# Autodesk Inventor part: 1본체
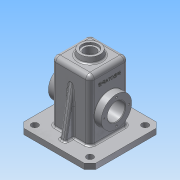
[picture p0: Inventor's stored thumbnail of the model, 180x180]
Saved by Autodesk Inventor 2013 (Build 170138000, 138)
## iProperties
Created: 2016-02
Part Number: 1본체
Material: 알루미늄 6061
Document SubType Name: Modeling
Designer: Administrator
Density: 2.71 g/cm^3
Mass: 929.197 g
Surface Area: 1052.48 cm^2
Volume: 342.877 cm^3
Author: Administrator
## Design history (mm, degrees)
sketch "스케치1"
  geometry: L1 (-65, 65)-(65, 65); L2 (65, 65)-(65, -65); L3 (65, -65)-(-65, -65); L4 (-65, -65)-(-65, 65); L5 (-65, 65)-(65, -65); 2 further points
  constraints: 10 end point, 2 parallel, 1 coincident, 1 horizontal, 1 midpoint, 1 perpendicular
  dimensions: "d0" = 130 distance of L1.end L2.end; "d2" = 130 distance of L1.start L1.end
extrude "돌출1" new body sketch "스케치1" distance "d3" = 10; taper "d4" = 0 deg
chamfer "모따기1" distance "d5" = 10; stored, may be unused: second distance "d6" = 2, angle "d7" = 45 deg
sketch "스케치2"
  geometry: C1 r 6 at (-50, 50); 1 further point
  constraints: 1 centre point
  dimensions: "d8" = 50 horizontal distance of point (0, 0) C1.centre; "d9" = 50 horizontal distance of point (0, 0) C1.centre; "d10" = 12 diameter of C1
extrude "돌출2" cut sketch "스케치2" stored distance "d11" = 10; taper "d12" = 0 deg
sketch "스케치3"
  geometry: L1 (65, -55)-(55, -65) reference; L2 (-35, 35)-(35, 35); L3 (35, 35)-(35, -35); L4 (35, -35)-(-35, -35); L5 (-35, -35)-(-35, 35); L6 (-35, 35)-(35, -35); 2 further points
  constraints: 10 end point, 2 parallel, 2 perpendicular, 1 coincident, 1 horizontal, 1 midpoint
  dimensions: "d19" = 70 distance of L2.end L3.end
extrude "돌출3" join sketch "스케치3" distance "d21" = 110; taper "d22" = 0 deg
sketch "스케치4"
  geometry: L1 (35, -35)-(35, 35) reference; L2 (35, 35)-(-35, 35) reference; L3 (-35, 35)-(-35, -35) reference; L4 (-35, -35)-(35, -35) reference; L5 (-30, 30)-(30, 30); L6 (30, 30)-(30, -30); L7 (30, -30)-(-30, -30); L8 (-30, -30)-(-30, 30); 1 further point
  constraints: 8 end point, 3 other
  dimensions: "d23" = 5 distance between parallel lines of L1 L6
extrude "돌출4" cut sketch "스케치4" distance "d24" = 115; taper "d25" = 0 deg
sketch "스케치5"
  geometry: L1 (0, 0)-(-110, 0) reference; L2 (10, 35)-(-45, 35); C1 r 27.5 at (-45, 35)
  constraints: 2 end point, 1 centre point, 1 coincident, 1 parallel
  dimensions: "d26" = 55 distance of L2.start L2.end; "d27" = 55 diameter of C1
extrude "돌출5" join sketch "스케치5" distance "d28" = 13; taper "d29" = 0 deg
sketch "스케치6"
  geometry: L1 (0, 0)-(-22.5, 0); C1 r 27.5 at (0, 0) reference; 2 further points
  constraints: 2 end point, 1 coincident, 1 horizontal
  dimensions: "d30" = 22.5 distance of L1.start L1.end
hole "구멍1" sketch "스케치6" at (-22.5, 0) diameter "d31" = 3.242; stored, may be unused: countersink angle "d35" = 90 deg, drill point angle "d37" = 118 deg; dims "d32" = 8, "d33" = 4, "d34" = 2, "d36" = 10
sketch "스케치7"
  geometry: C1 r 27.5 at (0, 0) reference; C2 r 16 at (0, 0); 1 further point
  constraints: 1 centre point, 1 coincident
  dimensions: "d42" = 32 diameter of C2
extrude "돌출6" cut sketch "스케치7" stored distance "d44" = 13; taper "d45" = 0 deg
sketch "스케치8"
  geometry: L1 (-30, 0)-(-30, 115) reference; L2 (-48, 71)-(-30, 71) reference; L3 (-35, 82.5)-(-48, 82.5) reference; L4 (-30, 82.5)-(-23, 75.5); L5 (-23, 75.5)-(-23, 71); L6 (-23, 71)-(-30, 71); L7 (-35, 27.5)-(-48, 27.5) reference; L8 (-30, 82.5)-(-30, 71); L9 (-48, 39)-(-48, 71) reference; L10 (-48, 55)-(-30, 55); 1 further point
  constraints: 10 end point, 4 perpendicular, 2 point on line, 1 midpoint
  dimensions: "d46" = 7 distance between parallel lines of L5 L1; "d47" = 135 deg angle of L1 L4; "d48" = 55 distance from line of L4.start L7
revolve "회전1" sketch "스케치8" stored, may be unused: angle "d49" = 90 deg
sketch "스케치9"
  geometry: C1 r 27.5 at (0, 0) reference; C2 r 16 at (0, 0); 1 further point
  constraints: 1 centre point, 1 coincident
  dimensions: "d51" = 32 diameter of C2
extrude "돌출7" cut sketch "스케치9" stored distance "d53" = 13; taper "d54" = 0 deg
chamfer "모따기2" distance "d55" = 1; stored, may be unused: second distance "d56" = 2, angle "d57" = 45 deg
sketch "스케치10"
  geometry: C1 r 20 at (0, 0); 1 further point
  constraints: 1 centre point, 1 coincident
  dimensions: "d59" = 40 diameter of C1
extrude "돌출8" join sketch "스케치10" distance "d61" = 10; taper "d62" = -10 deg
sketch "스케치11"
  geometry: C1 r 18.237 at (0, 0) reference; C2 r 14 at (0, 0)
  constraints: 1 centre point, 1 coincident
  dimensions: "d63" = 28 diameter of C2
extrude "돌출9" cut sketch "스케치11" distance "d65" = 4; taper "d66" = 0 deg
sketch "스케치12"
  geometry: C1 r 14 at (0, 0) reference; C2 r 10.5 at (0, 0)
  constraints: 1 centre point, 1 coincident
  dimensions: "d67" = 21 diameter of C2
extrude "돌출10" cut sketch "스케치12" stored distance "d69" = 4; taper "d70" = 0 deg
fillet "모깎기4" dims "d71" = 3
sketch "스케치13"
  geometry: L1 (35, 10)-(35, 120) reference; L2 (44, 10)-(56, 10) reference; L3 (55, 10)-(-55, 10) reference; L4 (35, 95.069)-(50, 10); L5 (65, 10)-(65, 0) reference; L6 (35, 95.069)-(35, 10); L7 (35, 10)-(50, 10); 1 further point
  constraints: 6 end point, 2 collinear, 2 point on line
  dimensions: "d72" = 10 deg angle of L5 L4; "d73" = 15 distance from line of L4.end L5
extrude "돌출11" join sketch "스케치13" stored distance "d74" = 10; taper "d75" = 0 deg
fillet "모깎기5" dims "d76" = 8
fillet "모깎기6" dims "d77" = 8
fillet "모깎기7" dims "d78" = 0.5
fillet "모깎기8" dims "d79" = 0.5
fillet "모깎기9" dims "d80" = 3
fillet "모깎기10" dims "d81" = 3
fillet "모깎기11" dims "d82" = 3
fillet "모깎기12" dims "d83" = 3
fillet "모깎기13" dims "d84" = 3
node "작업 평면1"
sketch "스케치14"
  geometry: L1 (-18, 8.763)-(-18, 45.237) reference; C1 r 17 at (57, 27) reference; 2 further points
  constraints: 1 horizontal alignment, 1 other
  dimensions: "d86" = 30 distance from line of point (12, 27) L1
feature "엠보싱1" sketch "스케치14" dims "d87" = 0.5, "d88" = 0
node "솔리드1"
pattern_linear "직사각형 패턴1" dims "d15" = 100
pattern_circular "원형 패턴1" dims angle "d39" = 360 deg
mirror "대칭1"
mirror "대칭2"
mirror "대칭3"
other parameters: "d85" = 55.25
